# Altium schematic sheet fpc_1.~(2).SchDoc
size A; SheetNumber: 1; SheetTotal: 1
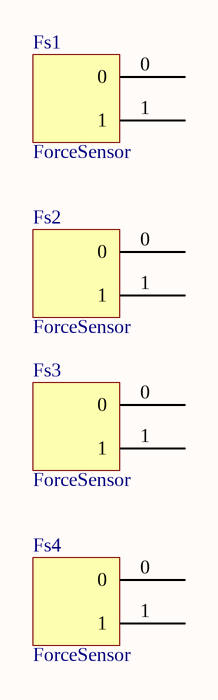
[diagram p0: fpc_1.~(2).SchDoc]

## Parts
Fs1  ForceSensor  [sensor_connector]
Fs2  ForceSensor  [sensor_connector]
Fs3  ForceSensor  [sensor_connector]
Fs4  ForceSensor  [sensor_connector]

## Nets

Not connected (* = marked no-connect by the designer): Fs1 0 1; Fs2 0 1; Fs3 0 1; Fs4 0 1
